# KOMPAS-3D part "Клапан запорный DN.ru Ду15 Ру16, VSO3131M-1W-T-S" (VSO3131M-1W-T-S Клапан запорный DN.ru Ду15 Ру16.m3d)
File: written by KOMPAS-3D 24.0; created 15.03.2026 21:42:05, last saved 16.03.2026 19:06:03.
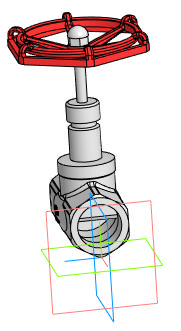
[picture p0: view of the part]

Document properties: Автор: artiomk228874@gmail.com; Полное имя файла: VSO3131M-1W-T-S Клапан запорный DN.ru Ду15 Ру16.cdw

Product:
- Body: Тело 1  | qty 1
    Масса: 0.243693
- Part/product: Клапан запорный DN.ru Ду15 Ру16  | designation VSO3131M-1W-T-S
    Масса: 0.31
    Раздел спецификации: Прочие изделия
    Форматы листов документа: A2
    Примечание: D100-03669
    additional columns: 94d3474e-3e6e-4ddd-ad0b-ef51eb5e31da; VSO3131M-1W-T-S; Сталь 10 ГОСТ 1050-2013; artiomk228874@gmail.com; c; Шероховатость не задана; Да

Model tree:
1. Операция без истории:1

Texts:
  VSO3131M-1W-T-S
